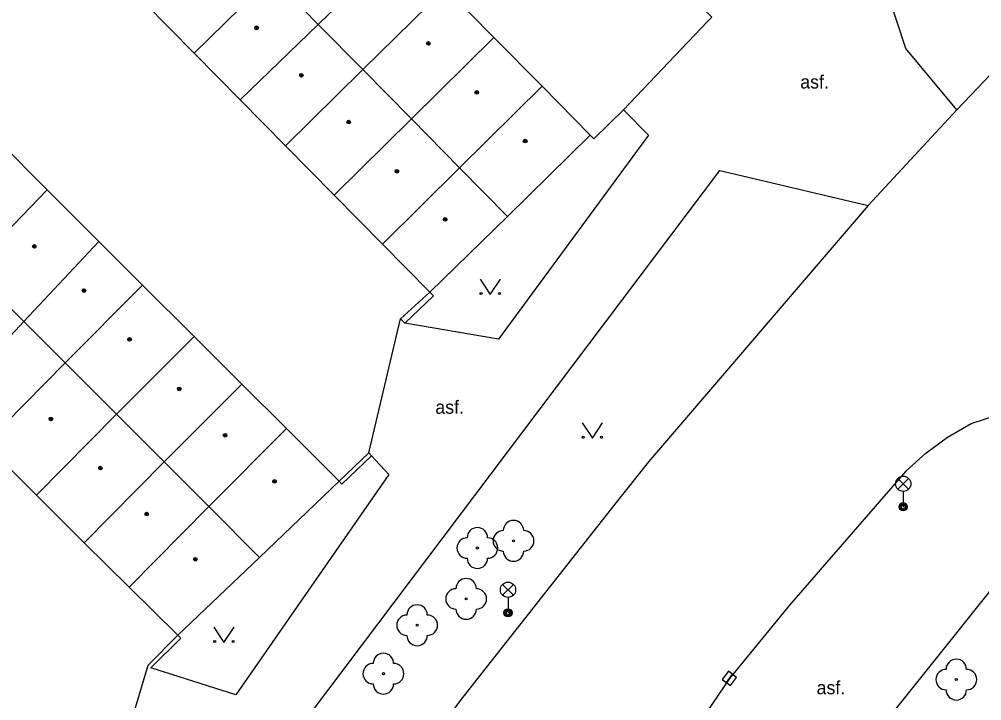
# Model space of a CAD drawing. Extents: x -598233 to -596890, y -1157848 to -1156431.
# Drawn here: x -597157.8 to -597110.67, y -1157074.38 to -1157041.02 of the extents above; entities that cross this region are included whole.
import ezdxf

# ---------------------------------------------------------------- set-up
doc = ezdxf.new("R2010")
doc.units = 0
for name, color, linetype in [('Level 10', 7, 'Continuous'), ('Level 11', 7, 'Continuous'), ('Level 22', 7, 'Continuous'), ('Level 27', 7, 'Continuous'), ('Level 33', 7, 'Continuous'), ('Level 36', 7, 'Continuous'), ('Level 39', 7, 'Continuous'), ('Level 40', 7, 'Continuous'), ('Level 5', 7, 'Continuous'), ('Level 7', 7, 'Continuous'), ('Level 8', 7, 'Continuous')]:
    doc.layers.add(name, color=color, linetype=linetype)

msp = doc.modelspace()

# ---------------------------------------------------------------- linework, layer by layer
at = {"layer": 'Level 10'}
for points in [[(-597108.51, -1157041.92), (-597111.9, -1157045.45)], [(-597111.9, -1157045.45), (-597116.24, -1157050.13)], [(-597116.24, -1157050.13), (-597126.99, -1157062.68), (-597128.64, -1157064.75)], [(-597114.4, -1157063.14), (-597113.42, -1157062.25), (-597112.35, -1157061.47), (-597111.2, -1157060.81), (-597109.69, -1157060.32), (-597108.43, -1157060.04)], [(-597114.4, -1157063.14), (-597120.09, -1157069.7), (-597123.03, -1157073.28), (-597126.11, -1157077.82)], [(-597128.64, -1157064.75), (-597136.2199, -1157074.37), (-597141.13, -1157081.1), (-597147.71, -1157091.5), (-597152.58, -1157100.4099)]]:
    msp.add_lwpolyline(points, dxfattribs=at)
at = {"layer": 'Level 11'}
for points in [[(-597111.9, -1157045.45), (-597114.39, -1157042.45), (-597115.2199, -1157039.9), (-597115.33, -1157038.3)], [(-597128.2199, -1157045.46), (-597126.99, -1157046.7), (-597134.34, -1157056.67), (-597138.92, -1157055.9)], [(-597158.78, -1157095.07), (-597149.84, -1157083.35), (-597123.5, -1157048.42), (-597122.46, -1157048.6599), (-597116.24, -1157050.13)], [(-597140.69, -1157062.24), (-597139.13, -1157055.69)], [(-597140.55, -1157062.38), (-597139.7, -1157063.3), (-597147.2, -1157074.08), (-597151.35, -1157072.77)], [(-597120.24, -1157081.48), (-597108.77, -1157067.15)], [(-597153.55, -1157079.52), (-597151.49, -1157072.63)]]:
    msp.add_lwpolyline(points, dxfattribs=at)
at = {"layer": 'Level 22'}
for centre in [(-597133.6, -1157066.55), (-597135.37, -1157066.9), (-597135.92, -1157069.39), (-597138.32, -1157070.68), (-597139.9699, -1157073.05), (-597111.92, -1157073.34)]:
    msp.add_circle(centre, 0.05, dxfattribs=at)
for centre, start, end in [((-597133.6, -1157066.05), 0, 180), ((-597135.37, -1157066.4), 0, 180), ((-597134.1, -1157066.55), 90, 270), ((-597133.1, -1157066.55), 270, 90), ((-597135.87, -1157066.9), 90, 270), ((-597134.87, -1157066.9), 270, 90), ((-597133.6, -1157067.05), 180, 0), ((-597135.37, -1157067.4), 180, 0), ((-597135.92, -1157068.89), 0, 180), ((-597136.42, -1157069.39), 90, 270), ((-597135.42, -1157069.39), 270, 90), ((-597138.32, -1157070.18), 0, 180), ((-597135.92, -1157069.89), 180, 0), ((-597138.82, -1157070.68), 90, 270), ((-597137.82, -1157070.68), 270, 90), ((-597138.32, -1157071.18), 180, 0), ((-597139.9699, -1157072.55), 0, 180), ((-597111.92, -1157072.84), 0, 180), ((-597140.4699, -1157073.05), 90, 270), ((-597139.4699, -1157073.05), 270, 90), ((-597112.42, -1157073.34), 90, 270), ((-597111.42, -1157073.34), 270, 90), ((-597139.9699, -1157073.55), 180, 0), ((-597111.92, -1157073.84), 180, 0)]:
    msp.add_arc(centre, 0.5, start, end, dxfattribs=at)
at = {"layer": 'Level 27'}
msp.add_line((-597123.1796, -1157073.4803), (-597122.8804, -1157073.0797), dxfattribs=at)
msp.add_lwpolyline([(-597122.9793, -1157073.6299), (-597122.6801, -1157073.2293), (-597123.0807, -1157072.9301), (-597123.3799, -1157073.3307)], close=True, dxfattribs=at)
at = {"layer": 'Level 33'}
for p, q in [((-597114.785, -1157064.02), (-597114.255, -1157063.49)), ((-597114.785, -1157063.49), (-597114.255, -1157064.02)), ((-597114.52, -1157064.13), (-597114.52, -1157064.88)), ((-597134.135, -1157069.21), (-597133.605, -1157068.68)), ((-597134.135, -1157068.68), (-597133.605, -1157069.21)), ((-597133.87, -1157069.32), (-597133.87, -1157070.07))]:
    msp.add_line(p, q, dxfattribs=at)
for centre, radius in [((-597114.52, -1157063.755), 0.375), ((-597114.52, -1157064.88), 0.2), ((-597114.52, -1157064.88), 0.1445), ((-597114.52, -1157064.88), 0.0876), ((-597133.87, -1157068.945), 0.375), ((-597133.87, -1157070.07), 0.2), ((-597133.87, -1157070.07), 0.1445), ((-597133.87, -1157070.07), 0.0876)]:
    msp.add_circle(centre, radius, dxfattribs=at)
at = {"layer": 'Level 36'}
for points in [[(-597135.24, -1157053.74), (-597134.74, -1157054.49), (-597134.24, -1157053.74)], [(-597130.24, -1157060.78), (-597129.74, -1157061.53), (-597129.24, -1157060.78)], [(-597148.28, -1157070.78), (-597147.78, -1157071.53), (-597147.28, -1157070.78)]]:
    msp.add_lwpolyline(points, dxfattribs=at)
for centre in [(-597135.1902, -1157054.4398), (-597134.2908, -1157054.4398), (-597130.1902, -1157061.4798), (-597129.2908, -1157061.4798), (-597148.2302, -1157071.4798), (-597147.3308, -1157071.4798)]:
    msp.add_circle(centre, 0.05, dxfattribs=at)
at = {"layer": 'Level 39'}
for centre, radius in [((-597146.18, -1157041.44), 0.09), ((-597146.18, -1157041.44), 0.0398), ((-597137.77, -1157042.2), 0.09), ((-597137.77, -1157042.2), 0.0398), ((-597143.99, -1157043.76), 0.09), ((-597143.99, -1157043.76), 0.0398), ((-597135.4, -1157044.6), 0.09), ((-597135.4, -1157044.6), 0.0398), ((-597141.67, -1157046.05), 0.09), ((-597141.67, -1157046.05), 0.0398), ((-597133.03, -1157046.98), 0.09), ((-597133.03, -1157046.98), 0.0398), ((-597139.31, -1157048.46), 0.09), ((-597139.31, -1157048.46), 0.0398), ((-597136.95, -1157050.82), 0.09), ((-597136.95, -1157050.82), 0.0398), ((-597157.06, -1157052.14), 0.09), ((-597157.06, -1157052.14), 0.0398), ((-597154.63, -1157054.3), 0.09), ((-597154.63, -1157054.3), 0.0398), ((-597152.4, -1157056.69), 0.09), ((-597152.4, -1157056.69), 0.0398), ((-597149.9699, -1157059.11), 0.09), ((-597149.9699, -1157059.11), 0.0398), ((-597156.25, -1157060.58), 0.09), ((-597156.25, -1157060.58), 0.0398), ((-597147.7199, -1157061.38), 0.09), ((-597147.7199, -1157061.38), 0.0398), ((-597153.83, -1157062.99), 0.09), ((-597153.83, -1157062.99), 0.0398), ((-597145.3, -1157063.64), 0.09), ((-597145.3, -1157063.64), 0.0398), ((-597151.56, -1157065.24), 0.09), ((-597151.56, -1157065.24), 0.0398), ((-597149.18, -1157067.45), 0.09), ((-597149.18, -1157067.45), 0.0398)]:
    msp.add_circle(centre, radius, dxfattribs=at)
at = {"layer": 'Level 5'}
for points in [[(-597139.08, -1157037.32), (-597143.1599, -1157041.27)], [(-597145.44, -1157038.95), (-597149.23, -1157042.68)], [(-597145.44, -1157038.95), (-597143.1599, -1157041.27)], [(-597136.93, -1157039.5), (-597140.9699, -1157043.48)], [(-597136.93, -1157039.5), (-597134.56, -1157041.9099)], [(-597151.68, -1157040.2), (-597149.23, -1157042.68)], [(-597143.1599, -1157041.27), (-597146.98, -1157044.9699)], [(-597143.1599, -1157041.27), (-597140.9699, -1157043.48)], [(-597134.56, -1157041.9099), (-597138.6, -1157045.9)], [(-597134.56, -1157041.9099), (-597132.2, -1157044.3)], [(-597149.23, -1157042.68), (-597146.98, -1157044.9699)], [(-597140.9699, -1157043.48), (-597144.76, -1157047.2199)], [(-597140.9699, -1157043.48), (-597138.6, -1157045.9)], [(-597132.2, -1157044.3), (-597136.24, -1157048.29)], [(-597132.2, -1157044.3), (-597129.84, -1157046.7)], [(-597146.98, -1157044.9699), (-597144.76, -1157047.2199)], [(-597138.6, -1157045.9), (-597142.38, -1157049.63)], [(-597138.6, -1157045.9), (-597136.24, -1157048.29)], [(-597129.84, -1157046.7), (-597133.89, -1157050.67)], [(-597158.82, -1157046.98), (-597156.44, -1157049.37)], [(-597144.76, -1157047.2199), (-597142.38, -1157049.63)], [(-597136.24, -1157048.29), (-597140.02, -1157052.02)], [(-597136.24, -1157048.29), (-597133.89, -1157050.67)], [(-597156.44, -1157049.37), (-597160.1599, -1157053.2199)], [(-597156.44, -1157049.37), (-597153.9, -1157051.89)], [(-597142.38, -1157049.63), (-597140.02, -1157052.02)], [(-597133.89, -1157050.67), (-597137.69, -1157054.38)], [(-597153.9, -1157051.89), (-597157.57, -1157055.82)], [(-597153.9, -1157051.89), (-597151.76, -1157054.03)], [(-597140.02, -1157052.02), (-597137.69, -1157054.38)], [(-597160.1599, -1157053.2199), (-597157.57, -1157055.82)], [(-597151.76, -1157054.03), (-597155.55, -1157057.84)], [(-597151.76, -1157054.03), (-597149.24, -1157056.54)], [(-597157.57, -1157055.82), (-597161.4099, -1157059.92)], [(-597157.57, -1157055.82), (-597155.55, -1157057.84)], [(-597149.24, -1157056.54), (-597153.04, -1157060.35)], [(-597149.24, -1157056.54), (-597146.9, -1157058.88)], [(-597155.55, -1157057.84), (-597159.48, -1157061.82)], [(-597155.55, -1157057.84), (-597153.04, -1157060.35)], [(-597146.9, -1157058.88), (-597150.7, -1157062.68)], [(-597146.9, -1157058.88), (-597144.7199, -1157061.05)], [(-597153.04, -1157060.35), (-597156.96, -1157064.32)], [(-597153.04, -1157060.35), (-597150.7, -1157062.68)], [(-597144.7199, -1157061.05), (-597148.52, -1157064.87)], [(-597144.7199, -1157061.05), (-597142.14, -1157063.63)], [(-597159.48, -1157061.82), (-597156.96, -1157064.32)], [(-597150.7, -1157062.68), (-597154.62, -1157066.64)], [(-597150.7, -1157062.68), (-597148.52, -1157064.87)], [(-597142.14, -1157063.63), (-597146.04, -1157067.36)], [(-597156.96, -1157064.32), (-597154.62, -1157066.64)], [(-597148.52, -1157064.87), (-597152.42, -1157068.81)], [(-597148.52, -1157064.87), (-597146.04, -1157067.36)], [(-597154.62, -1157066.64), (-597152.42, -1157068.81)], [(-597146.04, -1157067.36), (-597150.04, -1157071.17)], [(-597152.42, -1157068.81), (-597150.04, -1157071.17)]]:
    msp.add_lwpolyline(points, dxfattribs=at)
at = {"layer": 'Level 7'}
for points in [[(-597125.16, -1157037.14), (-597124.95, -1157037.36), (-597126.13, -1157038.66), (-597123.89, -1157040.91), (-597124.1, -1157041.13)], [(-597128.22, -1157045.46), (-597129.66, -1157046.87), (-597129.84, -1157046.7)], [(-597139.13, -1157055.69), (-597137.69, -1157054.38)], [(-597137.69, -1157054.38), (-597137.51, -1157054.56), (-597138.92, -1157055.9)], [(-597138.92, -1157055.9), (-597139.13, -1157055.69)], [(-597142.14, -1157063.63), (-597140.69, -1157062.24)], [(-597140.55, -1157062.38), (-597142, -1157063.78), (-597142.14, -1157063.63)], [(-597140.69, -1157062.24), (-597140.55, -1157062.38)], [(-597151.49, -1157072.63), (-597150.04, -1157071.17)], [(-597150.04, -1157071.17), (-597149.89, -1157071.31), (-597151.35, -1157072.77)]]:
    msp.add_lwpolyline(points, dxfattribs=at)
at = {"layer": 'Level 8'}
msp.add_lwpolyline([(-597128.22, -1157045.46), (-597124.1, -1157041.13)], dxfattribs=at)

# ---------------------------------------------------------------- texts
at = {"layer": 'Level 40'}
for p in [(-597119.56, -1157044.4099), (-597137.43, -1157060.33), (-597118.76, -1157074.06)]:
    msp.add_text('asf.', height=0.65, dxfattribs=at).set_placement(p)

doc.saveas('drawing.dxf')
